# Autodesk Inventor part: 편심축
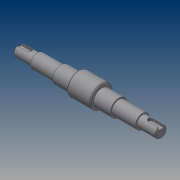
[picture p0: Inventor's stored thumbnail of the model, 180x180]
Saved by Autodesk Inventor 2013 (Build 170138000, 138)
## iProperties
Created: 2014-12
Part Number: 편심축
Material: Generic
Document SubType Name: Modeling
Designer: CAD-B18
Density: 1 g/cm^3
Author: CAD-B18
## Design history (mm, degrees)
sketch "스케치1"
  geometry: L1 (-75.5, 0)-(75.5, 0); L2 (-75.5, 0)-(-75.5, 6); L3 (-75.5, 6)-(-55.5, 6); L4 (-55.5, 6)-(-55.5, 7.5); L5 (-55.5, 7.5)-(-30.5, 7.5); L6 (-30.5, 7.5)-(-30.5, 9); L7 (-30.5, 9)-(30.5, 9); L8 (12.5, 9)-(12.5, 9); L9 (30.5, 9)-(30.5, 7.5); L10 (30.5, 7.5)-(55.5, 7.5); L11 (55.5, 7.5)-(55.5, 6); L12 (55.5, 6)-(75.5, 6); L13 (75.5, 6)-(75.5, 0); L14 (-81.94, 11.03)-(-61.5, 11.03); L15 (-61.5, 11.03)-(-61.5, 3); L16 (-61.5, 3)-(-81.94, 3); L17 (-81.94, 3)-(-81.94, 11.03); L18 (61.5, 8.25)-(80.021, 8.25); L19 (80.021, 8.25)-(80.021, 3); L20 (80.021, 3)-(61.5, 3); L21 (61.5, 3)-(61.5, 8.25); L22 (-12.5, 13)-(12.5, 13); L23 (12.5, 13)-(12.5, 1); L24 (12.5, 1)-(-12.5, 1); L25 (-12.5, 1)-(-12.5, 13); 2 further points
  constraints: 50 end point, 11 perpendicular, 8 parallel, 4 horizontal, 2 coincident, 1 midpoint, 1 point on line
  dimensions: "d0" = 151 distance of L1.start L1.end; "d1" = 6 distance of L1.start L2.end; "d2" = 20 distance of L2.end L3.end; "d4" = 1.5 distance of L3.end L4.end; "d5" = 25 distance of L4.end L5.end; "d6" = 1.5 distance of L5.end L6.end; "d7" = 18 distance of L7.end L8.end; "d8" = 25 distance of L9.end L10.end; "d9" = 12 diameter of L12 L1; "d10" = 15 diameter of L10 L1; "d12" = 20 distance between parallel lines of L11 L13; "d13" = 14 distance between parallel lines of L2 L15; "d14" = 3 distance between parallel lines of L3 L16; "d15" = 14 distance between parallel lines of L21 L13; "d16" = 3 distance between parallel lines of L12 L20; "d18" = 2 diameter of L24 L1; "d20" = 18 distance between parallel lines of L6 L25; "d21" = 18 distance between parallel lines of L9 L23; "d30" = 24 diameter of L22 L24
revolve "회전1" stored, may be unused: angle "d22" = 90 deg
revolve "회전2" stored, may be unused: angle "d23" = 90 deg
extrude "돌출1" cut sketch "스케치1" stored distance "d24" = 5; taper "d25" = 0 deg
fillet "모깎기1" dims "d26" = 2.5
chamfer "모따기1" distance "d27" = 1; stored, may be unused: second distance "d28" = 2, angle "d29" = 45 deg
node "솔리드1"
